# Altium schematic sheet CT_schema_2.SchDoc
size 276 x 169 mm
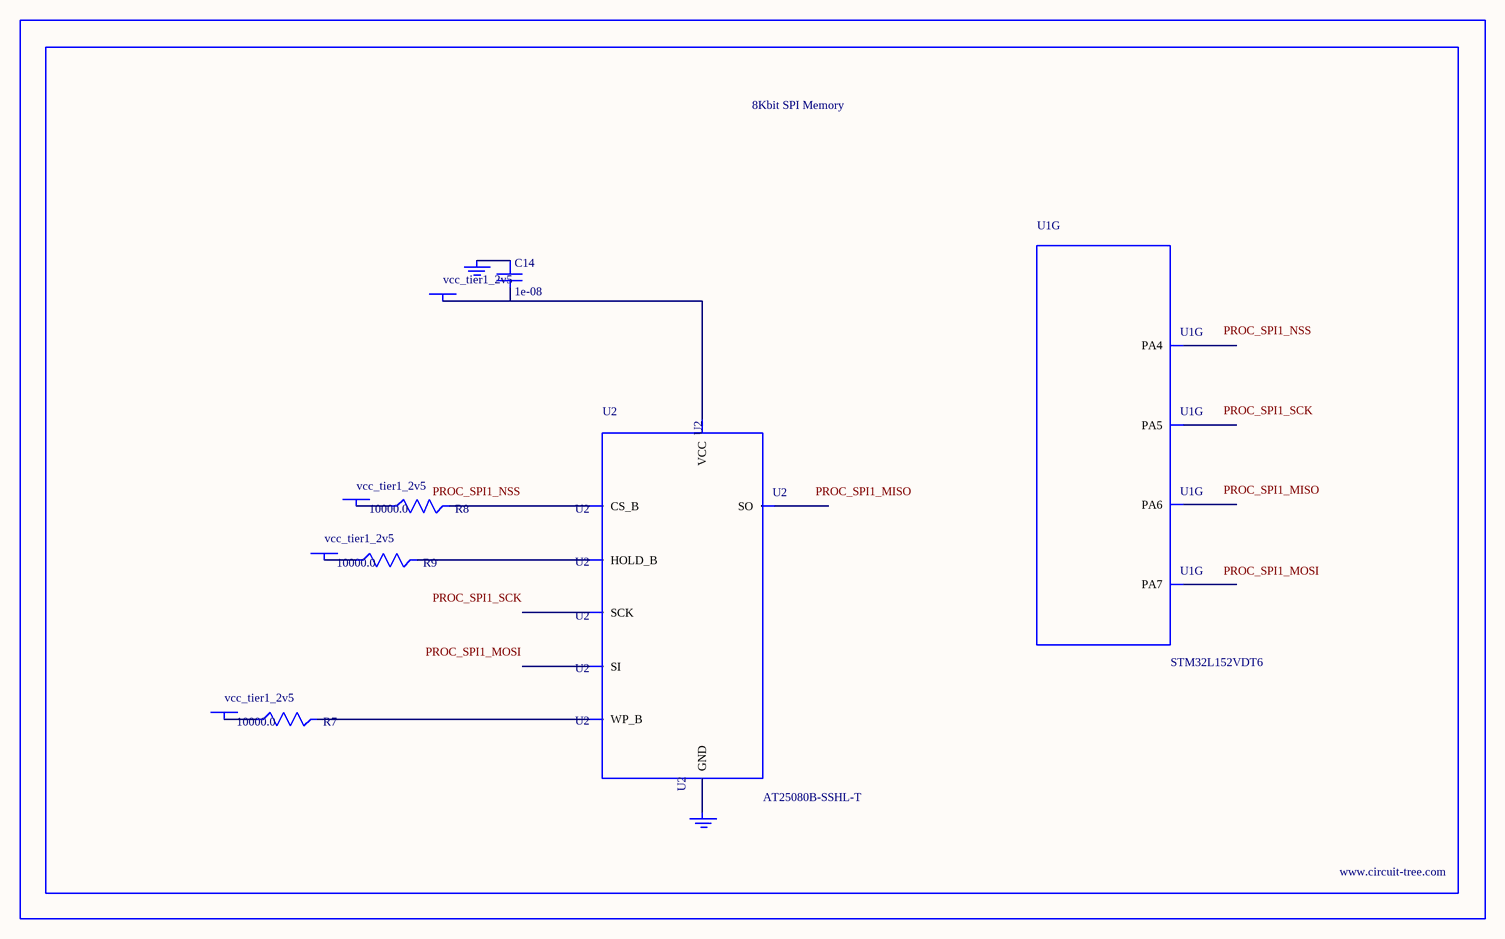
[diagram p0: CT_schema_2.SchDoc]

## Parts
BORDER1  (no value)
C14  1e-08  [C0402]
GND_INSTANCE_1_0  (no value)
GND_INSTANCE_1_1  (no value)
POWER_INSTANCE_1_0  vcc_tier1_2v5
POWER_INSTANCE_1_1  vcc_tier1_2v5
POWER_INSTANCE_1_2  vcc_tier1_2v5
POWER_INSTANCE_1_3  vcc_tier1_2v5
R7  10000.0  [R0603]
R8  10000.0  [R0603]
R9  10000.0  [R0603]
U1  STM32L152VDT6  [LQFP100]  (part G of 10)
U2  AT25080B-SSHL-T  [SOIC-8]

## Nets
NetC14_1: C14.1 GND_INSTANCE_1_0.0(GND)
NetC14_2: C14.2 POWER_INSTANCE_1_3.0(PWR) U2.8(VCC)
NetGND_INSTANCE_1_1_0: GND_INSTANCE_1_1.0(GND) U2.4(GND)
NetPOWER_INSTANCE_1_0_0: POWER_INSTANCE_1_0.0(PWR) R8.1
NetPOWER_INSTANCE_1_1_0: POWER_INSTANCE_1_1.0(PWR) R7.1
NetPOWER_INSTANCE_1_2_0: POWER_INSTANCE_1_2.0(PWR) R9.1
NetR7_2: R7.2 U2.3(WP_B)
NetR8_2: R8.2 U2.1(CS_B)
NetR9_2: R9.2 U2.7(HOLD_B)

Not connected (* = marked no-connect by the designer): U1 29(PA4) 30(PA5) 31(PA6) 32(PA7); U2 2(SO) 5(SI) 6(SCK)

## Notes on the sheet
- Labels drawn without touching a wire or pin: PROC_SPI1_MISO, PROC_SPI1_MOSI, PROC_SPI1_NSS, PROC_SPI1_SCK

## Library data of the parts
BORDER1 = BORDER_PAGE1
C14 = C0402C103K3RAC
GND_INSTANCE_1_0 GND_INSTANCE_1_1 = GND
POWER_INSTANCE_1_0-POWER_INSTANCE_1_3 = PWR
R7-R9 = RC0603JR-0710KL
